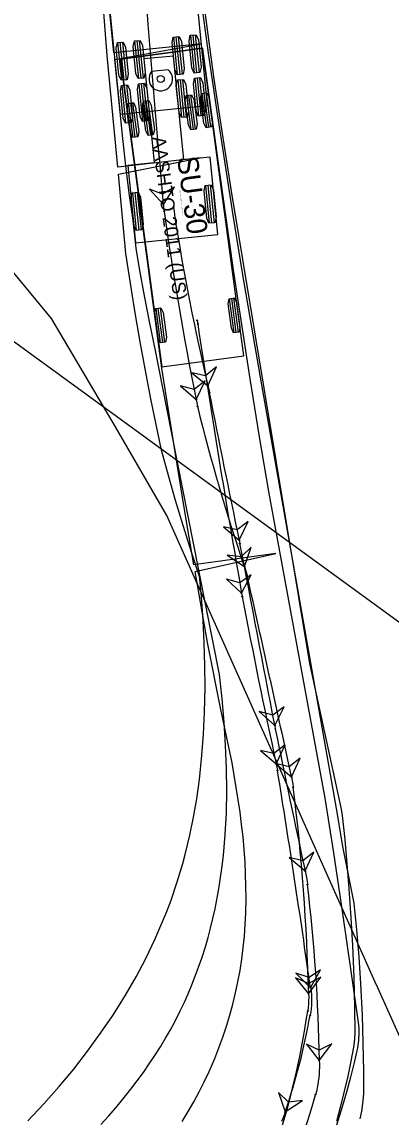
# Model space of a CAD drawing. Extents: x 2096670 to 2098561, y 684033 to 689893.
# Drawn here: x 2097666.2 to 2097701.9, y 685901.1 to 686007 of the extents above; entities that cross this region are included whole.
import ezdxf

# ---------------------------------------------------------------- set-up
doc = ezdxf.new("R2010")
doc.units = 0
for name, color, linetype in [('Default', 7, 'Continuous'), ('Old_Level_63', 7, 'Continuous'), ('Scratch_Level_4', 7, 'Continuous')]:
    doc.layers.add(name, color=color, linetype=linetype)

msp = doc.modelspace()

# ---------------------------------------------------------------- linework, layer by layer
at = {"layer": 'Default'}
msp.add_line((2097525.41, 686077.96), (2097723.95, 685933.46), dxfattribs=at)
at = {"layer": 'Old_Level_63'}
for p, q in [((2097671.46, 686040.33), (2097675.67, 685998.04)), ((2097684.13, 685998.88), (2097679.92, 686041.17)), ((2097681.23, 686001.86), (2097680.87, 686005.51)), ((2097681.46, 686001.88), (2097681.1, 686005.53)), ((2097681.69, 686001.91), (2097681.32, 686005.55)), ((2097682.87, 686002.02), (2097682.51, 686005.67)), ((2097683.1, 686002.05), (2097682.74, 686005.69)), ((2097683.33, 686002.07), (2097682.97, 686005.72)), ((2097675.83, 686001.32), (2097675.46, 686004.97)), ((2097676.05, 686001.34), (2097675.69, 686004.99)), ((2097683.64, 686004.43), (2097675.71, 686003.36)), ((2097676.28, 686001.37), (2097675.92, 686005.02)), ((2097677.47, 686001.48), (2097677.1, 686005.13)), ((2097677.7, 686001.51), (2097677.33, 686005.16)), ((2097677.92, 686001.53), (2097677.56, 686005.18)), ((2097687.62, 685974.69), (2097683.64, 686004.43)), ((2097675.71, 686003.36), (2097679.69, 685973.63)), ((2097680.82, 686003.66), (2097677.97, 686003.38)), ((2097677.97, 686003.38), (2097678.97, 685993.34)), ((2097681.82, 685993.63), (2097680.82, 686003.66)), ((2097680.33, 686002.33), (2097678.72, 686002.17)), ((2097678.11, 685997.36), (2097677.75, 686001.01)), ((2097678.34, 685997.38), (2097677.97, 686001.03)), ((2097681.65, 685997.71), (2097681.28, 686001.36)), ((2097681.87, 685997.74), (2097681.51, 686001.39)), ((2097682.1, 685997.76), (2097681.74, 686001.41)), ((2097683.29, 685997.88), (2097682.92, 686001.53)), ((2097683.52, 685997.9), (2097683.15, 686001.55)), ((2097683.74, 685997.92), (2097683.38, 686001.57)), ((2097676.24, 685997.18), (2097675.88, 686000.82)), ((2097676.47, 685997.2), (2097676.1, 686000.85)), ((2097676.7, 685997.22), (2097676.33, 686000.87)), ((2097677.88, 685997.34), (2097677.52, 686000.99)), ((2097684.04, 685996.74), (2097683.59, 686000.05)), ((2097684.24, 685996.77), (2097683.8, 686000.08)), ((2097684.45, 685996.8), (2097684.01, 686000.1)), ((2097676.93, 685995.79), (2097676.49, 685999.1)), ((2097677.14, 685995.82), (2097676.7, 685999.12)), ((2097677.35, 685995.85), (2097676.9, 685999.15)), ((2097678.42, 685995.99), (2097677.98, 685999.3)), ((2097678.63, 685996.02), (2097678.18, 685999.32)), ((2097678.83, 685996.05), (2097678.39, 685999.35)), ((2097682.55, 685996.54), (2097682.11, 685999.85)), ((2097682.76, 685996.57), (2097682.31, 685999.88)), ((2097682.96, 685996.6), (2097682.52, 685999.9)), ((2097675.67, 685998.04), (2097684.13, 685998.88)), ((2097684.13, 685998.88), (2097684.13, 685998.88)), ((2097684.38, 685993.88), (2097681.82, 685993.63)), ((2097685.12, 685986.42), (2097684.38, 685993.88)), ((2097678.97, 685993.34), (2097676.42, 685993.09)), ((2097676.42, 685993.09), (2097677.16, 685985.63)), ((2097677.27, 685986.81), (2097676.91, 685990.46)), ((2097677.5, 685986.83), (2097677.14, 685990.48)), ((2097677.73, 685986.86), (2097677.36, 685990.5)), ((2097684.32, 685987.51), (2097683.96, 685991.16)), ((2097684.55, 685987.53), (2097684.18, 685991.18)), ((2097684.78, 685987.56), (2097684.41, 685991.21)), ((2097677.16, 685985.63), (2097685.12, 685986.42)), ((2097685.12, 685986.42), (2097685.12, 685986.42)), ((2097686.69, 685976.92), (2097686.25, 685980.23)), ((2097686.9, 685976.95), (2097686.46, 685980.25)), ((2097687.11, 685976.98), (2097686.66, 685980.28)), ((2097679.59, 685975.97), (2097679.15, 685979.27)), ((2097679.8, 685976), (2097679.35, 685979.3)), ((2097680, 685976.02), (2097679.56, 685979.33)), ((2097679.69, 685973.63), (2097687.62, 685974.69)), ((2097687.62, 685974.69), (2097687.62, 685974.69))]:
    msp.add_line(p, q, dxfattribs=at)
for points in [[(2097673.82, 685900.44), (2097674.55, 685901.25), (2097675.25, 685902.05), (2097676.07, 685903.05), (2097676.71, 685903.85), (2097677.33, 685904.66), (2097677.92, 685905.47), (2097678.49, 685906.29), (2097679.03, 685907.11), (2097679.56, 685907.93), (2097680.05, 685908.76), (2097680.53, 685909.59), (2097680.98, 685910.42), (2097681.48, 685911.41), (2097681.88, 685912.24), (2097682.25, 685913.07), (2097682.6, 685913.91), (2097682.94, 685914.76), (2097683.26, 685915.62), (2097683.56, 685916.5), (2097683.91, 685917.58), (2097684.17, 685918.49), (2097684.41, 685919.4), (2097684.64, 685920.33), (2097684.85, 685921.27), (2097685.21, 685923.2), (2097685.5, 685925.18), (2097685.65, 685926.41), (2097685.83, 685928.45), (2097685.94, 685930.53), (2097685.98, 685932.66), (2097685.95, 685934.83), (2097685.87, 685937.04), (2097685.72, 685939.29), (2097685.52, 685941.57), (2097685.26, 685943.9), (2097683.29, 685954), (2097680.19, 685969.63), (2097679.1, 685975.22), (2097678.55, 685977.85), (2097678.04, 685980.48), (2097677.55, 685983.12), (2097677.22, 685985.11), (2097676.93, 685987.76), (2097676.56, 685990.4), (2097676.22, 685993.04), (2097675.92, 685995.69), (2097675.15, 686003.32), (2097683.54, 686004.83), (2097675.08, 686003.98), (2097673.63, 686018.54)], [(2097683.35, 686011.97), (2097684.01, 686006.7), (2097684.74, 686001.44), (2097685.52, 685996.17), (2097686.4, 685990.61), (2097693.97, 685944.96), (2097697.02, 685930.89), (2097697.13, 685930.3), (2097697.38, 685927.96), (2097697.59, 685925.61), (2097697.78, 685923.23), (2097697.97, 685920.4), (2097698.12, 685917.72), (2097698.24, 685914.65), (2097698.32, 685911.67), (2097698.35, 685909.39), (2097698.31, 685908.63), (2097698.21, 685907.9), (2097697.96, 685906.54), (2097697.66, 685905.1), (2097697.33, 685903.64), (2097696.97, 685902.19), (2097696.59, 685900.73)], [(2097683.33, 685953.39), (2097682.59, 685955.64), (2097681.75, 685958.3), (2097681.03, 685960.71), (2097680.34, 685963.13), (2097679.67, 685965.58), (2097679.15, 685968.06), (2097678.65, 685970.55), (2097678.1, 685973.45), (2097677.62, 685976.05), (2097677.17, 685978.67), (2097676.73, 685981.29), (2097676.22, 685984.58), (2097675.51, 685992.25), (2097683.4, 685993.82), (2097675.45, 685992.92), (2097675.21, 685995.63), (2097674.67, 686001.02), (2097674.43, 686003.72), (2097674, 686009.13)], [(2097683.43, 686009.45), (2097684.19, 686003.93), (2097684.95, 685998.72), (2097685.75, 685993.51), (2097686.57, 685988.3), (2097687.48, 685982.73), (2097688.36, 685977.47), (2097689.32, 685971.9), (2097696.63, 685930.43), (2097697.16, 685927.29), (2097698.14, 685922.46), (2097698.25, 685921.81), (2097698.51, 685919.23), (2097698.73, 685916.64), (2097698.9, 685914.02), (2097699.05, 685910.99), (2097699.14, 685908.29), (2097699.18, 685905.54), (2097699.18, 685903.43), (2097699.13, 685902.73), (2097698.99, 685901.72), (2097698.83, 685900.99)], [(2097681.67, 685900.73), (2097682.25, 685901.67), (2097682.79, 685902.62), (2097683.31, 685903.58), (2097683.8, 685904.56), (2097684.27, 685905.55), (2097684.81, 685906.81), (2097685.22, 685907.84), (2097685.6, 685908.88), (2097685.95, 685909.92), (2097686.27, 685910.98), (2097686.56, 685912.06), (2097686.83, 685913.14), (2097687.06, 685914.22), (2097687.26, 685915.31), (2097687.43, 685916.42), (2097687.57, 685917.52), (2097687.69, 685918.62), (2097687.77, 685919.74), (2097687.82, 685920.86), (2097687.84, 685922.3), (2097687.83, 685923.47), (2097687.8, 685924.65), (2097687.74, 685925.82), (2097687.66, 685927.01), (2097687.55, 685928.21), (2097687.41, 685929.41), (2097687.26, 685930.61), (2097686.5, 685935.37), (2097685.42, 685940.53), (2097684.11, 685947.01), (2097682.91, 685953.86), (2097690.73, 685955.6), (2097682.8, 685954.52), (2097681.9, 685959.84), (2097681.02, 685965.19), (2097679.71, 685973.51), (2097676.9, 685994.43), (2097675.71, 686003.36), (2097683.64, 686004.43), (2097683.68, 686004.1), (2097683.68, 686004.1)], [(2097683.68, 686004.1), (2097685.11, 685993.54), (2097685.85, 685988.26), (2097686.61, 685983), (2097687.4, 685977.73), (2097688.21, 685972.48), (2097689.12, 685966.87), (2097690.01, 685961.6), (2097690.48, 685958.96), (2097695.44, 685931.97), (2097696.28, 685926.68), (2097697.16, 685920.83), (2097697.97, 685915.24), (2097698.69, 685910.05), (2097698.73, 685909.67), (2097698.74, 685909.3), (2097698.71, 685908.55), (2097698.61, 685907.85), (2097698.29, 685906.42), (2097697.93, 685904.99), (2097697.55, 685903.56), (2097697.14, 685902.14), (2097696.57, 685900.38)], [(2097679.85, 685989.32), (2097680.92, 685991.01), (2097679.76, 685990.32), (2097678.5, 685990.79), (2097679.85, 685989.32)], [(2097679.85, 685989.32), (2097679.88, 685988.99), (2097679.93, 685988.66)], [(2097680.84, 685989.01), (2097680.88, 685988.68), (2097680.92, 685988.35), (2097680.97, 685988.02)], [(2097683.13, 685978.12), (2097683.17, 685977.79)], [(2097684.15, 685971.79), (2097684.97, 685973.62), (2097683.92, 685972.77), (2097682.6, 685973.06), (2097684.15, 685971.79)], [(2097683.01, 685970.47), (2097683.89, 685972.27), (2097682.82, 685971.45), (2097681.51, 685971.79), (2097683.01, 685970.47)], [(2097684.15, 685971.79), (2097684.23, 685971.47), (2097684.3, 685971.14)], [(2097683.01, 685970.47), (2097683.08, 685970.15), (2097683.15, 685969.82)], [(2097687.18, 685956.89), (2097688.05, 685958.7), (2097686.98, 685957.87), (2097685.66, 685958.19), (2097687.18, 685956.89)], [(2097687.18, 685956.89), (2097687.25, 685956.57)], [(2097687.68, 685954.33), (2097688.32, 685956.22), (2097687.36, 685955.28), (2097686.02, 685955.44), (2097687.68, 685954.33)], [(2097666.76, 685900.77), (2097668.31, 685902.42), (2097669.78, 685904.09), (2097671.2, 685905.79), (2097672.53, 685907.5), (2097673.79, 685909.24), (2097674.97, 685910.97), (2097675.53, 685911.84), (2097676.2, 685912.92), (2097677.21, 685914.69), (2097678.15, 685916.47), (2097679.02, 685918.29), (2097679.81, 685920.1), (2097680.18, 685921.01), (2097680.6, 685922.12), (2097681.2, 685923.88), (2097681.73, 685925.64), (2097681.97, 685926.52), (2097682.42, 685928.4), (2097682.77, 685930.12), (2097683.08, 685931.91), (2097683.34, 685933.77), (2097683.58, 685936.07), (2097683.74, 685938.15), (2097683.84, 685940.28), (2097683.89, 685942.64), (2097683.87, 685944.78), (2097683.81, 685946.95), (2097683.69, 685949.16), (2097683.54, 685951.41), (2097683.39, 685953.11), (2097683.33, 685953.39)], [(2097687.41, 685951.77), (2097688.34, 685953.54), (2097687.24, 685952.75), (2097685.94, 685953.12), (2097687.41, 685951.77)], [(2097687.68, 685954.33), (2097687.79, 685954.01), (2097687.88, 685953.69), (2097687.97, 685953.37)], [(2097687.41, 685951.77), (2097687.47, 685951.44)], [(2097690.61, 685938.99), (2097691.51, 685940.78), (2097690.42, 685939.98), (2097689.12, 685940.33), (2097690.61, 685938.99)], [(2097690.61, 685938.99), (2097690.67, 685938.67)], [(2097690.75, 685935.29), (2097691.61, 685937.1), (2097690.54, 685936.26), (2097689.23, 685936.58), (2097690.75, 685935.29)], [(2097692.23, 685934.01), (2097693.08, 685935.82), (2097692.02, 685934.98), (2097690.7, 685935.3), (2097692.23, 685934.01)], [(2097690.75, 685935.29), (2097690.82, 685934.96), (2097690.88, 685934.63)], [(2097692.23, 685934.01), (2097692.3, 685933.68), (2097692.36, 685933.35), (2097692.4, 685933.02)], [(2097693.54, 685924.93), (2097694.4, 685926.74), (2097693.33, 685925.91), (2097692.02, 685926.23), (2097693.54, 685924.93)], [(2097693.54, 685924.93), (2097693.61, 685924.61), (2097693.68, 685924.28), (2097693.73, 685923.95), (2097693.78, 685923.62)], [(2097694.07, 685913.64), (2097695.05, 685915.38), (2097693.93, 685914.63), (2097692.64, 685915.04), (2097694.07, 685913.64)], [(2097693.89, 685913.05), (2097695.07, 685914.67), (2097693.87, 685914.05), (2097692.63, 685914.61), (2097693.89, 685913.05)], [(2097694.07, 685913.64), (2097694.12, 685913.31), (2097694.15, 685912.97), (2097694.17, 685912.64), (2097694.17, 685912.31), (2097694.16, 685911.97), (2097694.13, 685911.64), (2097694.09, 685911.31), (2097694.03, 685910.98)], [(2097693.89, 685913.05), (2097693.9, 685912.72), (2097693.89, 685912.39), (2097693.88, 685912.05), (2097693.85, 685911.72), (2097693.8, 685911.39)], [(2097694.92, 685906.61), (2097696.12, 685908.22), (2097694.91, 685907.61), (2097693.68, 685908.18), (2097694.92, 685906.61)], [(2097694.92, 685906.61), (2097694.93, 685906.28), (2097694.93, 685905.95), (2097694.91, 685905.61), (2097694.89, 685905.28), (2097694.86, 685904.95), (2097694.82, 685904.62), (2097694.77, 685904.29), (2097694.71, 685903.96), (2097694.64, 685903.63), (2097694.56, 685903.31)], [(2097691.62, 685901.64), (2097693.29, 685902.75), (2097691.95, 685902.58), (2097690.98, 685903.53), (2097691.62, 685901.64)], [(2097691.62, 685901.64), (2097691.52, 685901.32), (2097691.39, 685901.01), (2097691.26, 685900.71)]]:
    msp.add_lwpolyline(points, dxfattribs=at)
for points in [[(2097681.75, 686001.91), (2097681.18, 686001.85), (2097680.95, 686002.35), (2097680.69, 686004.98), (2097680.81, 686005.5), (2097681.38, 686005.56), (2097681.6, 686005.07), (2097681.87, 686002.44)], [(2097683.39, 686002.07), (2097682.82, 686002.02), (2097682.6, 686002.51), (2097682.33, 686005.14), (2097682.45, 686005.67), (2097683.02, 686005.72), (2097683.25, 686005.23), (2097683.51, 686002.6)], [(2097676.34, 686001.37), (2097675.77, 686001.32), (2097675.55, 686001.81), (2097675.29, 686004.44), (2097675.41, 686004.96), (2097675.97, 686005.02), (2097676.2, 686004.53), (2097676.46, 686001.9)], [(2097677.98, 686001.54), (2097677.41, 686001.48), (2097677.19, 686001.97), (2097676.93, 686004.6), (2097677.05, 686005.13), (2097677.62, 686005.18), (2097677.84, 686004.69), (2097678.1, 686002.06)], [(2097678.39, 685997.39), (2097677.82, 685997.33), (2097677.6, 685997.83), (2097677.34, 686000.45), (2097677.46, 686000.98), (2097678.03, 686001.04), (2097678.25, 686000.54), (2097678.51, 685997.92)], [(2097682.16, 685997.76), (2097681.59, 685997.71), (2097681.37, 685998.2), (2097681.1, 686000.83), (2097681.23, 686001.36), (2097681.79, 686001.41), (2097682.02, 686000.92), (2097682.28, 685998.29)], [(2097683.8, 685997.93), (2097683.23, 685997.87), (2097683.01, 685998.37), (2097682.75, 686000.99), (2097682.87, 686001.52), (2097683.44, 686001.58), (2097683.66, 686001.08), (2097683.92, 685998.46)], [(2097676.75, 685997.23), (2097676.18, 685997.17), (2097675.96, 685997.66), (2097675.7, 686000.29), (2097675.82, 686000.82), (2097676.39, 686000.87), (2097676.61, 686000.38), (2097676.87, 685997.75)], [(2097684.5, 685996.81), (2097683.99, 685996.74), (2097683.77, 685997.18), (2097683.45, 685999.56), (2097683.54, 686000.04), (2097684.06, 686000.11), (2097684.28, 685999.67), (2097684.59, 685997.29)], [(2097677.4, 685995.85), (2097676.88, 685995.79), (2097676.67, 685996.23), (2097676.35, 685998.61), (2097676.44, 685999.09), (2097676.96, 685999.16), (2097677.17, 685998.72), (2097677.49, 685996.34)], [(2097678.88, 685996.05), (2097678.37, 685995.98), (2097678.15, 685996.43), (2097677.83, 685998.81), (2097677.93, 685999.29), (2097678.44, 685999.36), (2097678.66, 685998.92), (2097678.98, 685996.54)], [(2097683.01, 685996.61), (2097682.5, 685996.54), (2097682.28, 685996.98), (2097681.96, 685999.36), (2097682.06, 685999.84), (2097682.57, 685999.91), (2097682.79, 685999.47), (2097683.11, 685997.09)], [(2097677.78, 685986.86), (2097677.22, 685986.8), (2097676.99, 685987.3), (2097676.73, 685989.92), (2097676.85, 685990.45), (2097677.42, 685990.51), (2097677.64, 685990.02), (2097677.91, 685987.39)], [(2097679.85, 685989.32), (2097680.92, 685991.01), (2097679.76, 685990.32), (2097678.5, 685990.79)], [(2097684.83, 685987.56), (2097684.26, 685987.51), (2097684.04, 685988), (2097683.78, 685990.63), (2097683.9, 685991.16), (2097684.47, 685991.21), (2097684.69, 685990.72), (2097684.95, 685988.09)], [(2097687.16, 685976.98), (2097686.64, 685976.91), (2097686.43, 685977.36), (2097686.11, 685979.73), (2097686.2, 685980.22), (2097686.72, 685980.29), (2097686.93, 685979.85), (2097687.25, 685977.47)], [(2097680.05, 685976.03), (2097679.54, 685975.96), (2097679.32, 685976.4), (2097679, 685978.78), (2097679.1, 685979.27), (2097679.61, 685979.34), (2097679.83, 685978.89), (2097680.15, 685976.51)], [(2097684.15, 685971.79), (2097684.97, 685973.62), (2097683.92, 685972.77), (2097682.6, 685973.06)], [(2097683.01, 685970.47), (2097683.89, 685972.27), (2097682.82, 685971.45), (2097681.51, 685971.79)], [(2097687.18, 685956.89), (2097688.05, 685958.7), (2097686.98, 685957.87), (2097685.66, 685958.19)], [(2097687.68, 685954.33), (2097688.32, 685956.22), (2097687.36, 685955.28), (2097686.02, 685955.44)], [(2097687.41, 685951.77), (2097688.34, 685953.54), (2097687.24, 685952.75), (2097685.94, 685953.12)], [(2097690.61, 685938.99), (2097691.51, 685940.78), (2097690.42, 685939.98), (2097689.12, 685940.33)], [(2097690.75, 685935.29), (2097691.61, 685937.1), (2097690.54, 685936.26), (2097689.23, 685936.58)], [(2097692.23, 685934.01), (2097693.08, 685935.82), (2097692.02, 685934.98), (2097690.7, 685935.3)], [(2097693.54, 685924.93), (2097694.4, 685926.74), (2097693.33, 685925.91), (2097692.02, 685926.23)], [(2097694.07, 685913.64), (2097695.05, 685915.38), (2097693.93, 685914.63), (2097692.64, 685915.04)], [(2097693.89, 685913.05), (2097695.07, 685914.67), (2097693.87, 685914.05), (2097692.63, 685914.61)], [(2097694.92, 685906.61), (2097696.12, 685908.22), (2097694.91, 685907.61), (2097693.68, 685908.18)], [(2097691.62, 685901.64), (2097693.29, 685902.75), (2097691.95, 685902.58), (2097690.98, 685903.53)]]:
    msp.add_lwpolyline(points, close=True, dxfattribs=at)
for centre, radius in [((2097679.6, 686001.45), 0.34), ((2097679.85, 685989.32), 0.0417), ((2097679.85, 685989.32), 0.0417), ((2097679.93, 685988.66), 0.0417), ((2097679.93, 685988.66), 0.0417), ((2097680.84, 685989.01), 0.0417), ((2097680.97, 685988.02), 0.0417), ((2097680.97, 685988.02), 0.0417), ((2097683.13, 685978.12), 0.0417), ((2097683.17, 685977.79), 0.0417), ((2097683.17, 685977.79), 0.0417), ((2097684.15, 685971.79), 0.0417), ((2097684.15, 685971.79), 0.0417), ((2097683.01, 685970.47), 0.0417), ((2097683.01, 685970.47), 0.0417), ((2097684.3, 685971.14), 0.0417), ((2097684.3, 685971.14), 0.0417), ((2097683.15, 685969.82), 0.0417), ((2097683.15, 685969.82), 0.0417), ((2097687.18, 685956.89), 0.0417), ((2097687.18, 685956.89), 0.0417), ((2097687.25, 685956.57), 0.0417), ((2097687.25, 685956.57), 0.0417), ((2097687.68, 685954.33), 0.0417), ((2097687.68, 685954.33), 0.0417), ((2097687.97, 685953.37), 0.0417), ((2097687.97, 685953.37), 0.0417), ((2097687.41, 685951.77), 0.0417), ((2097687.41, 685951.77), 0.0417), ((2097687.47, 685951.44), 0.0417), ((2097687.47, 685951.44), 0.0417), ((2097690.61, 685938.99), 0.0417), ((2097690.61, 685938.99), 0.0417), ((2097690.67, 685938.67), 0.0417), ((2097690.67, 685938.67), 0.0417), ((2097690.75, 685935.29), 0.0417), ((2097690.75, 685935.29), 0.0417), ((2097690.88, 685934.63), 0.0417), ((2097690.88, 685934.63), 0.0417), ((2097692.23, 685934.01), 0.0417), ((2097692.23, 685934.01), 0.0417), ((2097692.4, 685933.02), 0.0417), ((2097692.4, 685933.02), 0.0417), ((2097693.54, 685924.93), 0.0417), ((2097693.54, 685924.93), 0.0417), ((2097693.78, 685923.62), 0.0417), ((2097693.78, 685923.62), 0.0417), ((2097694.07, 685913.64), 0.0417), ((2097694.07, 685913.64), 0.0417), ((2097693.89, 685913.05), 0.0417), ((2097693.89, 685913.05), 0.0417), ((2097693.8, 685911.39), 0.0417), ((2097693.8, 685911.39), 0.0417), ((2097694.03, 685910.98), 0.0417), ((2097694.03, 685910.98), 0.0417), ((2097694.92, 685906.61), 0.0417), ((2097694.92, 685906.61), 0.0417), ((2097694.56, 685903.31), 0.0417), ((2097694.56, 685903.31), 0.0417), ((2097691.62, 685901.64), 0.0417), ((2097691.62, 685901.64), 0.0417)]:
    msp.add_circle(centre, radius, dxfattribs=at)
for centre, radius, start, end in [((2099104.41, 686119.61), 1430.51, 182.74116, 185.22576), ((2097679.6, 686001.45), 1.14, 140.6909, 50.6909), ((2097998.03, 686033.26), 321.22, 187.9821, 191.2725), ((2097902.43, 686023.07), 224.22, 188.9939, 193.219), ((2098842.02, 686153.27), 1172.06, 188.6105, 189.89975), ((2098521.99, 686133.46), 853.28, 190.96604, 191.94241), ((2097866.88, 686015.1), 189.23, 193.8442, 198.7329), ((2093116.77, 685074.89), 4654.75, 10.69845, 10.91866), ((2094484.28, 685238.07), 3282.58, 12.24023, 12.5863), ((2098308.01, 686069.22), 631.62, 190.7469, 192.24195), ((2098835.96, 686171.29), 1168.68, 191.48148, 192.16945), ((2096700.54, 685773.58), 1003.35, 8.02382, 9.23658), ((2097487.92, 685907.76), 206.04, 1.4728, 7.0435), ((2097534.41, 685904.33), 160.53, 0.8145, 6.9007), ((2097616.35, 685922.72), 78.27, 341.2075, 351.68), ((2097630.59, 685922.34), 64.45, 341.264, 349.8523), ((2097654.88, 685914.05), 41.11, 303.4719, 344.8548)]:
    msp.add_arc(centre, radius, start, end, dxfattribs=at)
at = {"layer": 'Scratch_Level_4'}
msp.add_line((2097720.64, 685868.7), (2097700.46, 685913.91), dxfattribs=at)
msp.add_lwpolyline([(2097700.46, 685913.9), (2097680.18, 685959.26), (2097675.22, 685967.85), (2097669.04, 685978.29), (2097664.35, 685983.99), (2097658.92, 685987.96), (2097652.56, 685989.34), (2097646.4, 685988.65), (2097638.64, 685984.85), (2097635.31, 685982.05), (2097610.66, 685955.38)], dxfattribs=at)

# ---------------------------------------------------------------- texts
at = {"layer": 'Old_Level_63'}
for s, height, p in [('AASHTO 2011 (US)', 1.3333, (2097678.73, 685995.82)), ('SU-30', 2, (2097681.18, 685993.86)), ('(c) 2023 Transoft Solutions, Inc. All rights reserved.', 0.08, (2097681.41, 685990.65))]:
    msp.add_text(s, height=height, rotation=277.6328, dxfattribs=at).set_placement(p)

doc.saveas('drawing.dxf')
